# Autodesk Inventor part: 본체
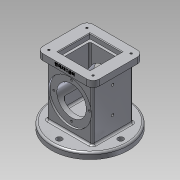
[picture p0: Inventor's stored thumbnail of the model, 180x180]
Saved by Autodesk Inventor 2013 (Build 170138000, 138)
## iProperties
Created: 2018-10
Part Number: 본체
Material: 알루미늄 6061
Document SubType Name: Modeling
Designer: hana-max10
Density: 2.40731 g/cm^3
Mass: 879.367 g
Surface Area: 748.201 cm^2
Volume: 365.29 cm^3
Author: hana-max10
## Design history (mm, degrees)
sketch "스케치1"
  geometry: C1 r 62.5 at (0, 0); 1 further point
  constraints: 1 centre point, 1 coincident
  dimensions: "d0" = 125 diameter of C1
extrude "돌출1" new body sketch "스케치1" distance "d2" = 10; taper "d3" = 0 deg
sketch "스케치2"
  geometry: L1 (-37, 33)-(37, 33); L2 (37, 33)-(37, -33); L3 (37, -33)-(-37, -33); L4 (-37, -33)-(-37, 33); L5 (-37, 33)-(37, -33); L6 (37, 33)-(-37, -33); C1 r 62.5 at (0, 0) reference
  constraints: 12 end point, 2 midpoint, 2 parallel, 1 horizontal, 1 perpendicular
  dimensions: "d4" = 74 distance of L2.end L3.end; "d7" = 66 distance of L1.end L2.end
extrude "돌출2" join sketch "스케치2" distance "d8" = 88; taper "d9" = 0 deg
sketch "스케치3"
  geometry: L1 (-46, 41)-(46, 41); L2 (46, 41)-(46, -41); L3 (46, -41)-(-46, -41); L4 (-46, -41)-(-46, 41); L5 (-46, 41)-(46, -41); L6 (46, 41)-(-46, -41); 1 further point
  constraints: 12 end point, 2 midpoint, 2 parallel, 1 horizontal, 1 perpendicular
  dimensions: "d10" = 92 distance of L1.start L1.end; "d12" = 82 distance of L1.end L2.end
extrude "돌출3" join sketch "스케치3" distance "d13" = 10; taper "d14" = 0 deg
sketch "스케치4"
  geometry: L1 (-26, 26)-(26, 26); L2 (26, 26)-(26, -26); L3 (26, -26)-(-26, -26); L4 (-26, -26)-(-26, 26); L5 (-26, 26)-(26, -26); L6 (26, 26)-(-26, -26); 1 further point
  constraints: 12 end point, 2 midpoint, 2 parallel, 1 horizontal, 1 perpendicular
  dimensions: "d15" = 52 distance of L1.start L1.end; "d17" = 52 distance of L1.end L2.end
extrude "돌출4" cut sketch "스케치4" distance "d18" = 8; taper "d19" = 0 deg
sketch "스케치6"
  geometry: L1 (-22, -22)-(22, -22); L2 (22, -22)-(22, 22); L3 (22, 22)-(-22, 22); L4 (-22, 22)-(-22, -22); L5 (-22, -22)-(22, 22); L6 (22, -22)-(-22, 22); 1 further point
  constraints: 12 end point, 2 midpoint, 2 parallel, 1 horizontal, 1 perpendicular
  dimensions: "d25" = 44 distance of L2.end L3.end; "d27" = 44 distance of L1.end L2.end
extrude "돌출5" cut sketch "스케치6" distance "d28" = 74; taper "d29" = 0 deg
fillet "모깎기1" dims "d37" = 3
node "작업 평면3"
sketch "스케치8"
  geometry: L1 (-88, 63)-(0, 63) reference; L2 (0, -3)-(-88, -3) reference; L3 (-98, 4)-(-98, 56) reference; L4 (-98, 4)-(-90, 4) reference; L5 (-90, 4)-(-90, 56) reference; L6 (-98, 56)-(-90, 56) reference; L7 (-90, 52)-(-16, 52) reference; L8 (-90, 8)-(-90, 52) reference; L9 (-90, 8)-(-16, 8) reference; L10 (10, -32.5)-(10, 92.5) reference; L11 (0, 92.5)-(0, -32.5) reference; L12 (10, -32.5)-(10, 92.5) reference; L13 (-88, -11)-(-88, 71) reference; L14 (-88, -11)-(-98, -11) reference; L15 (-98, 71)-(-98, -11) reference; L16 (-88, 71)-(-98, 71) reference; L17 (-44, -3)-(-44, 63); L18 (-44, -3)-(-79, -3); L19 (-79, 0)-(-79, -3); L20 (-79, 0)-(-68, 0); L21 (-68, 0)-(-68, 60); L22 (-68, 60)-(-79, 60); L23 (-79, 60)-(-79, 63); L24 (-79, 63)-(-44, 63); L25 (-16, 8)-(-16, 52) reference; 3 further points
  constraints: 16 end point, 3 horizontal, 3 vertical, 2 midpoint, 2 point on line
  dimensions: "d38" = 3 distance between parallel lines of L24 L22; "d40" = 3 distance between parallel lines of L2 L20; "d41" = 70 diameter of L19 L17; "d42" = 70 diameter of L23 L17; "d43" = 48 diameter of L21 L17
revolve "회전1" sketch "스케치8" stored, may be unused: angle "d44" = 90 deg
node "작업 평면4"
sketch "스케치12"
  geometry: L1 (10, 2)-(-5.521, 4.737); L2 (-8, 7.691)-(-8, 30); L3 (-8, 30)-(10, 30); L4 (10, 30)-(10, 2); A1 r 3 centre (-5, 7.691) between (-8, 7.691) and (-5.521, 4.737)
  constraints: 8 end point, 2 point on circle, 2 tangent, 2 vertical, 1 centre point, 1 horizontal
  dimensions: "d48" = 18 distance between parallel lines of L2 L4; "d50" = 80 deg angle of L4 L1; "d52" = 56 diameter of L1.start L3; "d53" = 3 radius of A1
revolve "회전2" sketch "스케치12" stored, may be unused: angle "d54" = 90 deg
sketch "스케치13"
  geometry: C1 r 24 at (0, 0) reference; 2 further points
  constraints: 1 vertical alignment
  dimensions: "d55" = 29 distance of C1.centre point (0, -29)
hole "구멍1" sketch "스케치13" at (0, -29) diameter "d56" = 3.242; stored, may be unused: countersink angle "d60" = 90 deg, drill point angle "d62" = 118 deg; dims "d57" = 4, "d58" = 4, "d59" = 2, "d61" = 6
sketch "스케치14"
  geometry: L1 (10, -32.5)-(10, 92.5) reference; 4 further points
  constraints: 2 horizontal alignment, 1 midpoint
  dimensions: "d66" = 37 distance from line of L1 point (-27, 30); "d67" = 43 distance of point (-70, 30) point (-27, 30)
hole "구멍2" sketch "스케치14" at (-27, 30), (-70, 30) diameter "d68" = 4.134; stored, may be unused: countersink angle "d72" = 90 deg, drill point angle "d74" = 0 deg; dims "d69" = 6, "d70" = 4, "d71" = 2, "d73" = 15
sketch "스케치15" dims "d75" = 100
  geometry: C1 r 62.5 at (0, 0) reference; C2 r 4.5 at (0, 50); 2 further points
  constraints: 2 coincident, 2 vertical alignment, 1 centre point, 2 other
  dimensions: "d77" = 9 diameter of C2
extrude "돌출6" cut sketch "스케치15" distance "d78" = 12; taper "d79" = 0 deg
fillet "모깎기2" dims "d83" = 10
sketch "스케치17"
  geometry: A1 r 10 centre (-36, 31) between (-36, 41) and (-46, 31) reference; A2 r 10 centre (-36, -31) between (-46, -31) and (-36, -41) reference; A3 r 10 centre (36, -31) between (36, -41) and (46, -31) reference; A4 r 10 centre (36, 31) between (46, 31) and (36, 41) reference; 5 further points
  constraints: 4 coincident
hole "구멍3" sketch "스케치17" at (-36, 31), (-36, -31), (36, -31), (36, 31) diameter "d84" = 3.242; stored, may be unused: countersink angle "d88" = 90 deg, drill point angle "d90" = 118 deg; dims "d85" = 4, "d86" = 4, "d87" = 2, "d89" = 6
fillet "모깎기3" dims "d91" = 3
fillet "모깎기4" dims "d92" = 3
fillet "모깎기5" dims "d93" = 3
chamfer "모따기1" distance "d94" = 1; stored, may be unused: second distance "d95" = 2, angle "d96" = 45 deg
fillet "모깎기6" dims "d97" = 3
sketch "스케치20"
  geometry: L1 (0, 10)-(72, 10) reference; L2 (-10, 10)-(-10, 0) reference; L3 (0, 10)-(-10, 10) reference; L4 (-10, 10)-(-10, 0) reference; L5 (-10, 0)-(0, 0) reference; L6 (0, 0)-(0, 10) reference; L7 (82, 10)-(72, 10) reference; L8 (72, 10)-(72, 0) reference; L9 (72, 0)-(82, 0) reference; L10 (82, 0)-(82, 10) reference; 2 further points
  constraints: 1 other
  dimensions: "d98" = 46 distance from line of point (36, 6) L2; "d99" = 4 distance from line of L1 point (36, 6)
feature "엠보싱1" sketch "스케치20" dims "d100" = 0.5, "d101" = 0
node "솔리드1"
pattern_circular "원형 패턴1" dims angle "d64" = 360 deg
mirror "대칭1"
pattern_circular "원형 패턴2" dims angle "d81" = 360 deg
node "투영된 루프7"
node "투영된 루프8"
node "투영된 루프9"
node "투영된 루프10"
node "투영된 루프12"
node "투영된 루프13"
